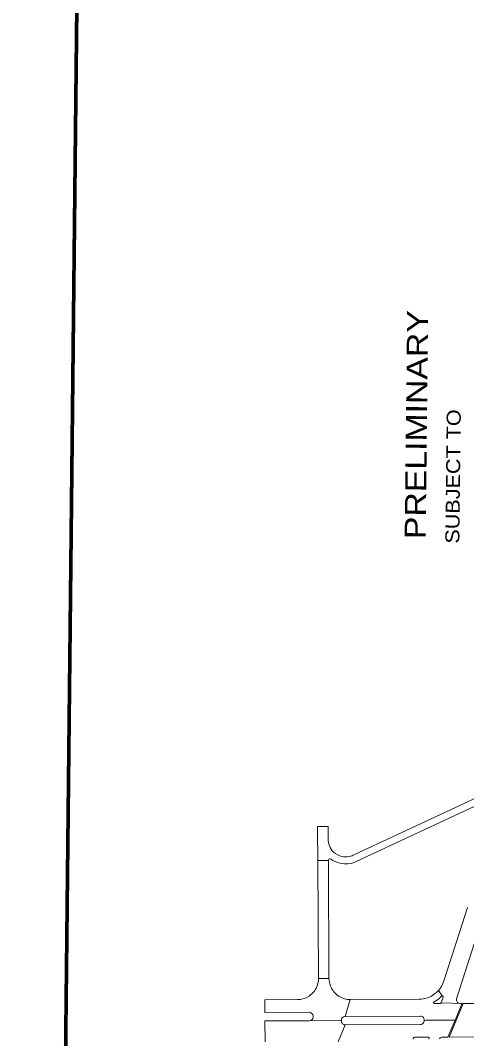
# Model space of a CAD drawing. Extents: x 2356576 to 2377878, y 6966390 to 6990634.
# Drawn here: x 2363518 to 2364785, y 6980469 to 6983363 of the extents above; entities that cross this region are included whole.
import ezdxf

# ---------------------------------------------------------------- set-up
doc = ezdxf.new("R2010")
doc.units = 0
doc.header["$LTSCALE"] = 7.1
for name, color, linetype, lineweight in [('19', 7, 'Continuous', 13), ('8', 7, 'Continuous', 13), ('9', 7, 'Continuous', 13)]:
    doc.layers.add(name, color=color, linetype=linetype, lineweight=lineweight)
doc.layers.add('5', color=7, linetype='Continuous')

msp = doc.modelspace()

# ---------------------------------------------------------------- linework, layer by layer
at = {"layer": '19', "lineweight": 40}
msp.add_lwpolyline([(2363758.773, 6990629.355), (2367158.576, 6990592.767), (2366922.891, 6968646.236), (2363523.088, 6968682.826)], close=True, dxfattribs=at)
at = {"layer": '8', "lineweight": 40}
for points in [[(2363753.827, 6990634.409), (2367163.63, 6990597.713), (2366927.837, 6968641.182), (2363518.034, 6968677.88)], [(2363758.773, 6990629.355), (2367158.576, 6990592.767), (2366922.891, 6968646.236), (2363523.088, 6968682.826)]]:
    msp.add_lwpolyline(points, close=True, dxfattribs=at)
at = {"layer": '9'}
for points in [[(2364820.882, 6981135.875), (2364471.57, 6980972.489), (2364463.498, 6980969.271), (2364457.076, 6980967.431), (2364448.692, 6980966.092), (2364437.988, 6980965.925), (2364426.214, 6980967.598), (2364418.9, 6980969.605), (2364411.764, 6980972.617), (2364405.342, 6980975.963), (2364400.629, 6980979.371), (2364398.206, 6980980.479), (2364396.244, 6980980.145), (2364394.282, 6980979.141), (2364393.39, 6980977.635), (2364392.855, 6980976.297), (2364392.68, 6980975.305), (2364362.65, 6980975.452), (2364362.215, 6981059.257), (2364362.215, 6981071.988), (2364391.894, 6981072.689), (2364391.918, 6981035.866), (2364391.963, 6981031.336), (2364392.676, 6981027.823), (2364393.747, 6981022.303), (2364395.53, 6981017.116), (2364397.85, 6981012.265), (2364400.347, 6981007.915), (2364403.737, 6981003.398), (2364407.304, 6980999.551), (2364412.656, 6980995.201), (2364419.257, 6980991.353), (2364425.144, 6980988.677), (2364430.495, 6980987.338), (2364435.847, 6980986.335), (2364440.664, 6980985.833), (2364446.194, 6980986), (2364451.367, 6980986.837), (2364456.006, 6980987.84), (2364460.109, 6980989.179), (2364463.098, 6980990.605), (2364780.248, 6981138.971), (2364812.002, 6981153.838)], [(2364787.558, 6980841.608), (2364764.846, 6980770.954), (2364720.623, 6980633.313), (2364716.663, 6980623.2), (2364712.694, 6980616.376), (2364709.056, 6980611.103), (2364705.417, 6980606.45), (2364715.825, 6980590.532), (2364716.538, 6980590.493), (2364717.088, 6980590.315), (2364717.553, 6980590.038), (2364718.011, 6980589.59), (2364718.362, 6980588.987), (2364718.506, 6980588.501), (2364718.463, 6980587.378), (2364713.34, 6980571.44), (2364772.643, 6980569.514), (2364766.428, 6980569.646), (2364762.001, 6980570.484), (2364759.488, 6980572.147), (2364757.271, 6980575.474), (2364756.385, 6980578.662), (2364756.875, 6980582.707), (2364806.743, 6980738.694)], [(2364420.584, 6980460.517), (2364440.125, 6980508.585), (2364437.744, 6980509.042), (2364436.368, 6980509.57), (2364434.618, 6980510.625), (2364433.306, 6980511.621), (2364432.056, 6980513.028), (2364430.93, 6980514.611), (2364430.055, 6980516.604), (2364429.68, 6980518.362), (2364429.493, 6980519.827), (2364429.466, 6980520.669), (2364337.882, 6980520.255), (2364212.718, 6980519.849), (2364212.913, 6980459.849)], [(2364420.584, 6980460.517), (2364440.125, 6980508.585), (2364653.513, 6980509.278), (2364655.839, 6980509.554), (2364659.05, 6980510.683), (2364661.218, 6980512.114), (2364662.904, 6980514.222), (2364664.269, 6980516.405), (2364665.072, 6980518.588), (2364665.232, 6980520.32), (2364665.313, 6980521.299), (2364670.927, 6980521.621), (2364752.59, 6980521.621), (2364732.452, 6980473.554), (2364715.2, 6980473.403), (2364712.346, 6980472.597), (2364710.05, 6980471.157), (2364708.259, 6980469.204)], [(2364678.044, 6980468.184), (2364678.749, 6980470.377), (2364678.952, 6980471.157), (2364678.94, 6980471.647), (2364678.853, 6980472.005), (2364678.701, 6980472.341), (2364678.314, 6980472.827), (2364678.133, 6980472.974), (2364677.811, 6980473.163), (2364677.157, 6980473.353), (2364676.623, 6980473.351), (2364668.066, 6980473.325), (2364664.618, 6980473.313), (2364637.01, 6980473.224), (2364635.459, 6980472.405), (2364633.689, 6980470.369), (2364633.208, 6980468.138)]]:
    msp.add_lwpolyline(points, dxfattribs=at)
for points in [[(2364362.65, 6980975.452), (2364364.531, 6980640.473), (2364394.533, 6980640.301), (2364392.68, 6980975.305)], [(2364212.641, 6980543.847), (2364337.806, 6980544.253), (2364342.46, 6980543.81), (2364345.959, 6980540.857), (2364348.759, 6980537.43), (2364349.584, 6980534.464), (2364349.722, 6980530.468), (2364348.622, 6980526.857), (2364346.422, 6980523.763), (2364343.81, 6980521.7), (2364341.197, 6980520.797), (2364337.882, 6980520.255), (2364429.466, 6980520.669), (2364429.603, 6980522.216), (2364430.016, 6980524.537), (2364431.391, 6980527.373), (2364433.041, 6980529.178), (2364435.928, 6980531.241), (2364438.678, 6980532.273), (2364440.321, 6980532.586), (2364454.727, 6980580.633), (2364446.496, 6980581.024), (2364442.221, 6980581.803), (2364436.758, 6980583.251), (2364431.77, 6980584.922), (2364428.089, 6980586.815), (2364422.388, 6980589.933), (2364417.876, 6980593.163), (2364413.838, 6980596.504), (2364411.226, 6980599.176), (2364407.663, 6980603.074), (2364405.169, 6980606.638), (2364402.913, 6980610.202), (2364401.25, 6980613.208), (2364398.638, 6980618.665), (2364397.569, 6980622.006), (2364396.5, 6980625.459), (2364395.669, 6980628.8), (2364394.837, 6980634.145), (2364394.533, 6980640.301), (2364364.531, 6980640.337), (2364364.436, 6980635.036), (2364363.724, 6980629.802), (2364362.299, 6980623.231), (2364360.223, 6980617.442), (2364358.798, 6980614.101), (2364356.542, 6980609.757), (2364354.404, 6980606.416), (2364351.435, 6980602.519), (2364347.041, 6980597.507), (2364341.46, 6980592.941), (2364337.778, 6980590.157), (2364331.959, 6980586.705), (2364325.072, 6980583.698), (2364319.609, 6980582.139), (2364314.978, 6980581.025), (2364310.702, 6980580.468), (2364304.727, 6980580.141), (2364212.213, 6980579.839)], [(2364705.417, 6980606.45), (2364700.134, 6980600.904), (2364694.369, 6980596.4), (2364685.53, 6980590.453), (2364675.154, 6980585.768), (2364666.892, 6980583.426), (2364657.093, 6980581.804), (2364649.465, 6980581.266), (2364454.727, 6980580.633), (2364440.321, 6980532.586), (2364653.411, 6980533.278), (2364655.999, 6980533.119), (2364658.247, 6980532.291), (2364660.736, 6980530.861), (2364662.583, 6980529.129), (2364664.028, 6980526.946), (2364664.831, 6980524.612), (2364665.313, 6980521.299), (2364670.927, 6980521.621), (2364752.59, 6980521.621), (2364772.765, 6980569.732), (2364772.643, 6980569.514), (2364713.34, 6980571.44), (2364713.07, 6980570.601), (2364712.399, 6980569.794), (2364711.662, 6980569.551), (2364694.002, 6980569.411), (2364692.256, 6980569.912), (2364691.525, 6980571.521), (2364691.487, 6980572.795), (2364692.822, 6980574.119), (2364696.291, 6980576.218), (2364701.094, 6980578.921), (2364705.129, 6980581.984), (2364708.588, 6980584.687), (2364714.299, 6980589.828), (2364714.889, 6980590.256), (2364715.337, 6980590.438), (2364715.825, 6980590.532)], [(2364736.106, 6980473.474), (2364775.895, 6980569.652), (2364776.217, 6980569.457), (2364854.398, 6980569.554), (2365295.907, 6980571.365), (2365242.551, 6980475.198)]]:
    msp.add_lwpolyline(points, close=True, dxfattribs=at)

# ---------------------------------------------------------------- texts
at = {"layer": '5'}
for s, height, width, p in [('PRELIMINARY', 59.8, 1.2, (2364669.146, 6981888.667)), ('SUBJECT TO', 39.87, 1.15, (2364764.684, 6981876.004))]:
    msp.add_text(s, height=height, rotation=89.364, dxfattribs=dict(at, width=width)).set_placement(p)

doc.saveas('drawing.dxf')
